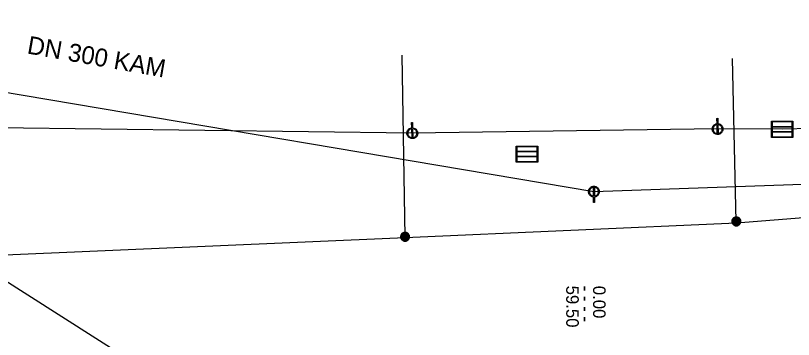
# Model space of a CAD drawing. Extents: x -818321 to -817653, y -1049725 to -1049329.
# Drawn here: x -818121.36 to -818077.89, y -1049423.87 to -1049405.76 of the extents above; entities that cross this region are included whole.
import ezdxf

# ---------------------------------------------------------------- set-up
doc = ezdxf.new("R2010")
doc.units = 0
doc.layers.add('Default', color=7, linetype='Continuous')
doc.layers.add('Level 0', color=7, linetype='Continuous')

msp = doc.modelspace()

# ---------------------------------------------------------------- linework, layer by layer
at = {"layer": 'Default'}
for points in [[(-818099.225, -1049412.037), (-818099.235, -1049411.736), (-818099.186, -1049411.735), (-818099.176, -1049412.035)], [(-818082.16, -1049411.806), (-818082.165, -1049411.506), (-818082.116, -1049411.505), (-818082.111, -1049411.805)], [(-818077.923, -1049412.573), (-818079.123, -1049412.574), (-818079.123, -1049411.673), (-818077.923, -1049411.673), (-818077.923, -1049412.573)], [(-818077.96, -1049411.961), (-818077.96, -1049411.71), (-818079.085, -1049411.71), (-818079.085, -1049411.961), (-818077.96, -1049411.961)], [(-818099.206, -1049412.585), (-818099.223, -1049412.088)], [(-818099.174, -1049412.086), (-818099.157, -1049412.583)], [(-818082.15, -1049412.355), (-818082.159, -1049411.857)], [(-818082.11, -1049411.856), (-818082.101, -1049412.354)], [(-818077.96, -1049412.246), (-818077.96, -1049411.998), (-818079.085, -1049411.998), (-818079.085, -1049412.246), (-818077.96, -1049412.246)], [(-818077.96, -1049412.283), (-818079.085, -1049412.283), (-818079.085, -1049412.536), (-818077.96, -1049412.536), (-818077.96, -1049412.283)], [(-818092.183, -1049413.953), (-818093.383, -1049413.954), (-818093.383, -1049413.053), (-818092.183, -1049413.053), (-818092.183, -1049413.953)], [(-818092.22, -1049413.341), (-818092.22, -1049413.09), (-818093.345, -1049413.09), (-818093.345, -1049413.341), (-818092.22, -1049413.341)], [(-818092.22, -1049413.626), (-818092.22, -1049413.378), (-818093.345, -1049413.378), (-818093.345, -1049413.626), (-818092.22, -1049413.626)], [(-818092.22, -1049413.663), (-818093.345, -1049413.663), (-818093.345, -1049413.916), (-818092.22, -1049413.916), (-818092.22, -1049413.663)], [(-818089.065, -1049415.853), (-818089.065, -1049415.356)], [(-818089.015, -1049415.356), (-818089.015, -1049415.853)], [(-818089.015, -1049415.904), (-818089.015, -1049416.205), (-818089.065, -1049416.205), (-818089.065, -1049415.904)]]:
    msp.add_lwpolyline(points, dxfattribs=at)
for points in [[(-818099.176, -1049412.035), (-818099.113, -1049412.037), (-818099.05, -1049412.07), (-818098.977, -1049412.107), (-818098.935, -1049412.177), (-818098.893, -1049412.247), (-818098.89, -1049412.325), (-818098.887, -1049412.403), (-818098.925, -1049412.477), (-818098.963, -1049412.55), (-818099.033, -1049412.591), (-818099.103, -1049412.632), (-818099.179, -1049412.635), (-818099.255, -1049412.638), (-818099.328, -1049412.602), (-818099.401, -1049412.565), (-818099.444, -1049412.495), (-818099.487, -1049412.424), (-818099.49, -1049412.346), (-818099.492, -1049412.268), (-818099.455, -1049412.195), (-818099.418, -1049412.122), (-818099.348, -1049412.08), (-818099.287, -1049412.043), (-818099.225, -1049412.037)], [(-818099.223, -1049412.088), (-818099.272, -1049412.093), (-818099.323, -1049412.124), (-818099.381, -1049412.158), (-818099.411, -1049412.219), (-818099.442, -1049412.279), (-818099.44, -1049412.344), (-818099.438, -1049412.409), (-818099.402, -1049412.468), (-818099.366, -1049412.527), (-818099.305, -1049412.557), (-818099.253, -1049412.583), (-818099.206, -1049412.585)], [(-818099.157, -1049412.583), (-818099.109, -1049412.577), (-818099.059, -1049412.548), (-818099, -1049412.514), (-818098.969, -1049412.453), (-818098.938, -1049412.391), (-818098.94, -1049412.326), (-818098.942, -1049412.261), (-818098.977, -1049412.203), (-818099.012, -1049412.145), (-818099.073, -1049412.115), (-818099.125, -1049412.088), (-818099.174, -1049412.086)], [(-818082.111, -1049411.805), (-818082.048, -1049411.808), (-818081.985, -1049411.842), (-818081.913, -1049411.88), (-818081.872, -1049411.951), (-818081.831, -1049412.022), (-818081.83, -1049412.1), (-818081.829, -1049412.178), (-818081.868, -1049412.251), (-818081.907, -1049412.324), (-818081.978, -1049412.364), (-818082.049, -1049412.404), (-818082.125, -1049412.405), (-818082.2, -1049412.406), (-818082.273, -1049412.369), (-818082.345, -1049412.332), (-818082.387, -1049412.26), (-818082.428, -1049412.189), (-818082.43, -1049412.11), (-818082.431, -1049412.033), (-818082.393, -1049411.96), (-818082.355, -1049411.888), (-818082.284, -1049411.848), (-818082.222, -1049411.811), (-818082.16, -1049411.806)], [(-818082.159, -1049411.857), (-818082.208, -1049411.862), (-818082.259, -1049411.891), (-818082.318, -1049411.925), (-818082.349, -1049411.985), (-818082.381, -1049412.045), (-818082.38, -1049412.11), (-818082.379, -1049412.175), (-818082.344, -1049412.234), (-818082.309, -1049412.294), (-818082.249, -1049412.325), (-818082.198, -1049412.351), (-818082.15, -1049412.355)], [(-818082.101, -1049412.354), (-818082.054, -1049412.349), (-818082.003, -1049412.32), (-818081.943, -1049412.287), (-818081.911, -1049412.227), (-818081.879, -1049412.166), (-818081.88, -1049412.101), (-818081.881, -1049412.036), (-818081.915, -1049411.977), (-818081.949, -1049411.919), (-818082.009, -1049411.887), (-818082.06, -1049411.859), (-818082.11, -1049411.856)], [(-818089.065, -1049415.904), (-818089.127, -1049415.9), (-818089.189, -1049415.865), (-818089.261, -1049415.826), (-818089.3, -1049415.754), (-818089.34, -1049415.683), (-818089.34, -1049415.605), (-818089.34, -1049415.526), (-818089.3, -1049415.454), (-818089.259, -1049415.382), (-818089.188, -1049415.343), (-818089.116, -1049415.305), (-818089.04, -1049415.305), (-818088.964, -1049415.305), (-818088.893, -1049415.343), (-818088.821, -1049415.382), (-818088.78, -1049415.454), (-818088.74, -1049415.526), (-818088.74, -1049415.605), (-818088.74, -1049415.683), (-818088.78, -1049415.754), (-818088.819, -1049415.826), (-818088.891, -1049415.865), (-818088.953, -1049415.9), (-818089.015, -1049415.904)], [(-818089.065, -1049415.356), (-818089.112, -1049415.36), (-818089.164, -1049415.387), (-818089.223, -1049415.42), (-818089.257, -1049415.48), (-818089.29, -1049415.54), (-818089.29, -1049415.605), (-818089.29, -1049415.67), (-818089.257, -1049415.729), (-818089.225, -1049415.788), (-818089.165, -1049415.821), (-818089.114, -1049415.85), (-818089.065, -1049415.853)], [(-818089.015, -1049415.853), (-818088.966, -1049415.85), (-818088.915, -1049415.821), (-818088.855, -1049415.788), (-818088.823, -1049415.729), (-818088.79, -1049415.67), (-818088.79, -1049415.605), (-818088.79, -1049415.54), (-818088.823, -1049415.48), (-818088.857, -1049415.42), (-818088.917, -1049415.387), (-818088.968, -1049415.36), (-818089.015, -1049415.356)], [(-818081.085, -1049417.015), (-818081.022, -1049417.015), (-818080.962, -1049417.047), (-818080.903, -1049417.079), (-818080.869, -1049417.139), (-818080.835, -1049417.199), (-818080.835, -1049417.265), (-818080.835, -1049417.33), (-818080.868, -1049417.389), (-818080.901, -1049417.449), (-818080.96, -1049417.482), (-818081.02, -1049417.515), (-818081.085, -1049417.515), (-818081.15, -1049417.515), (-818081.209, -1049417.482), (-818081.269, -1049417.449), (-818081.302, -1049417.389), (-818081.335, -1049417.33), (-818081.335, -1049417.265), (-818081.335, -1049417.199), (-818081.301, -1049417.139), (-818081.268, -1049417.079), (-818081.208, -1049417.047), (-818081.148, -1049417.015), (-818081.085, -1049417.015)], [(-818081.085, -1049417.038), (-818081.142, -1049417.038), (-818081.196, -1049417.067), (-818081.251, -1049417.096), (-818081.281, -1049417.151), (-818081.311, -1049417.206), (-818081.311, -1049417.265), (-818081.311, -1049417.324), (-818081.282, -1049417.378), (-818081.252, -1049417.431), (-818081.198, -1049417.461), (-818081.144, -1049417.491), (-818081.085, -1049417.491), (-818081.026, -1049417.491), (-818080.972, -1049417.461), (-818080.918, -1049417.431), (-818080.888, -1049417.378), (-818080.858, -1049417.324), (-818080.858, -1049417.265), (-818080.858, -1049417.206), (-818080.889, -1049417.151), (-818080.92, -1049417.096), (-818080.974, -1049417.067), (-818081.028, -1049417.038), (-818081.085, -1049417.038)], [(-818081.085, -1049417.055), (-818081.032, -1049417.055), (-818080.982, -1049417.082), (-818080.932, -1049417.109), (-818080.904, -1049417.16), (-818080.875, -1049417.21), (-818080.875, -1049417.265), (-818080.875, -1049417.319), (-818080.903, -1049417.369), (-818080.93, -1049417.419), (-818080.98, -1049417.447), (-818081.03, -1049417.474), (-818081.085, -1049417.474), (-818081.139, -1049417.474), (-818081.189, -1049417.447), (-818081.239, -1049417.419), (-818081.267, -1049417.369), (-818081.294, -1049417.319), (-818081.294, -1049417.265), (-818081.294, -1049417.21), (-818081.266, -1049417.16), (-818081.238, -1049417.109), (-818081.188, -1049417.082), (-818081.138, -1049417.055), (-818081.085, -1049417.055)], [(-818081.085, -1049417.077), (-818081.163, -1049417.077), (-818081.218, -1049417.132), (-818081.272, -1049417.187), (-818081.272, -1049417.265), (-818081.272, -1049417.343), (-818081.217, -1049417.397), (-818081.163, -1049417.452), (-818081.085, -1049417.452), (-818081.007, -1049417.452), (-818080.952, -1049417.397), (-818080.897, -1049417.343), (-818080.897, -1049417.265), (-818080.897, -1049417.187), (-818080.952, -1049417.132), (-818081.007, -1049417.077), (-818081.085, -1049417.077)], [(-818081.085, -1049417.1), (-818081.017, -1049417.1), (-818080.969, -1049417.148), (-818080.921, -1049417.196), (-818080.921, -1049417.264), (-818080.921, -1049417.332), (-818080.969, -1049417.38), (-818081.017, -1049417.428), (-818081.085, -1049417.428), (-818081.154, -1049417.428), (-818081.202, -1049417.38), (-818081.249, -1049417.332), (-818081.249, -1049417.264), (-818081.249, -1049417.196), (-818081.202, -1049417.148), (-818081.154, -1049417.1), (-818081.085, -1049417.1)], [(-818081.085, -1049417.12), (-818081.145, -1049417.12), (-818081.188, -1049417.162), (-818081.23, -1049417.204), (-818081.23, -1049417.264), (-818081.23, -1049417.324), (-818081.188, -1049417.366), (-818081.145, -1049417.408), (-818081.085, -1049417.408), (-818081.026, -1049417.408), (-818080.983, -1049417.366), (-818080.941, -1049417.324), (-818080.941, -1049417.264), (-818080.941, -1049417.204), (-818080.983, -1049417.162), (-818081.025, -1049417.12), (-818081.085, -1049417.12)], [(-818081.085, -1049417.14), (-818081.033, -1049417.14), (-818080.996, -1049417.176), (-818080.96, -1049417.213), (-818080.96, -1049417.265), (-818080.96, -1049417.317), (-818080.997, -1049417.353), (-818081.033, -1049417.39), (-818081.085, -1049417.39), (-818081.137, -1049417.39), (-818081.173, -1049417.353), (-818081.21, -1049417.317), (-818081.21, -1049417.265), (-818081.21, -1049417.213), (-818081.174, -1049417.176), (-818081.137, -1049417.14), (-818081.085, -1049417.14)], [(-818081.085, -1049417.163), (-818081.127, -1049417.163), (-818081.157, -1049417.193), (-818081.187, -1049417.222), (-818081.187, -1049417.264), (-818081.187, -1049417.307), (-818081.157, -1049417.336), (-818081.127, -1049417.366), (-818081.085, -1049417.366), (-818081.043, -1049417.366), (-818081.013, -1049417.336), (-818080.984, -1049417.307), (-818080.984, -1049417.264), (-818080.984, -1049417.222), (-818081.013, -1049417.193), (-818081.043, -1049417.163), (-818081.085, -1049417.163)], [(-818081.085, -1049417.18), (-818081.05, -1049417.18), (-818081.025, -1049417.205), (-818081.001, -1049417.229), (-818081.001, -1049417.264), (-818081.001, -1049417.3), (-818081.026, -1049417.324), (-818081.05, -1049417.349), (-818081.085, -1049417.349), (-818081.12, -1049417.349), (-818081.145, -1049417.324), (-818081.169, -1049417.3), (-818081.169, -1049417.264), (-818081.169, -1049417.229), (-818081.145, -1049417.205), (-818081.12, -1049417.18), (-818081.085, -1049417.18)], [(-818081.085, -1049417.202), (-818081.111, -1049417.202), (-818081.129, -1049417.22), (-818081.147, -1049417.239), (-818081.147, -1049417.265), (-818081.147, -1049417.291), (-818081.129, -1049417.309), (-818081.111, -1049417.327), (-818081.085, -1049417.327), (-818081.059, -1049417.327), (-818081.041, -1049417.309), (-818081.022, -1049417.291), (-818081.022, -1049417.265), (-818081.022, -1049417.239), (-818081.041, -1049417.22), (-818081.059, -1049417.202), (-818081.085, -1049417.202)], [(-818081.085, -1049417.226), (-818081.069, -1049417.226), (-818081.057, -1049417.237), (-818081.046, -1049417.248), (-818081.046, -1049417.265), (-818081.046, -1049417.281), (-818081.057, -1049417.292), (-818081.069, -1049417.304), (-818081.085, -1049417.304), (-818081.101, -1049417.304), (-818081.113, -1049417.292), (-818081.124, -1049417.281), (-818081.124, -1049417.265), (-818081.124, -1049417.248), (-818081.113, -1049417.237), (-818081.101, -1049417.226), (-818081.085, -1049417.226)], [(-818081.085, -1049417.241), (-818081.095, -1049417.241), (-818081.102, -1049417.248), (-818081.109, -1049417.255), (-818081.109, -1049417.265), (-818081.109, -1049417.274), (-818081.102, -1049417.281), (-818081.095, -1049417.288), (-818081.085, -1049417.288), (-818081.075, -1049417.288), (-818081.068, -1049417.281), (-818081.062, -1049417.274), (-818081.062, -1049417.265), (-818081.062, -1049417.255), (-818081.068, -1049417.248), (-818081.075, -1049417.241), (-818081.085, -1049417.241)], [(-818099.592, -1049417.874), (-818099.529, -1049417.874), (-818099.469, -1049417.906), (-818099.41, -1049417.938), (-818099.376, -1049417.999), (-818099.342, -1049418.059), (-818099.342, -1049418.124), (-818099.342, -1049418.189), (-818099.375, -1049418.249), (-818099.408, -1049418.308), (-818099.467, -1049418.341), (-818099.527, -1049418.374), (-818099.592, -1049418.374), (-818099.657, -1049418.374), (-818099.716, -1049418.341), (-818099.776, -1049418.308), (-818099.809, -1049418.249), (-818099.842, -1049418.189), (-818099.842, -1049418.124), (-818099.842, -1049418.059), (-818099.808, -1049417.999), (-818099.775, -1049417.938), (-818099.715, -1049417.906), (-818099.655, -1049417.874), (-818099.592, -1049417.874)], [(-818099.592, -1049417.897), (-818099.649, -1049417.897), (-818099.703, -1049417.927), (-818099.758, -1049417.956), (-818099.788, -1049418.01), (-818099.818, -1049418.065), (-818099.818, -1049418.124), (-818099.818, -1049418.183), (-818099.789, -1049418.237), (-818099.759, -1049418.291), (-818099.705, -1049418.321), (-818099.651, -1049418.351), (-818099.592, -1049418.351), (-818099.533, -1049418.351), (-818099.479, -1049418.321), (-818099.425, -1049418.291), (-818099.395, -1049418.237), (-818099.365, -1049418.183), (-818099.365, -1049418.124), (-818099.365, -1049418.065), (-818099.396, -1049418.01), (-818099.427, -1049417.956), (-818099.481, -1049417.927), (-818099.535, -1049417.897), (-818099.592, -1049417.897)], [(-818099.592, -1049417.914), (-818099.539, -1049417.914), (-818099.489, -1049417.941), (-818099.439, -1049417.968), (-818099.411, -1049418.019), (-818099.382, -1049418.069), (-818099.382, -1049418.124), (-818099.382, -1049418.179), (-818099.41, -1049418.228), (-818099.437, -1049418.278), (-818099.487, -1049418.306), (-818099.537, -1049418.333), (-818099.592, -1049418.333), (-818099.646, -1049418.333), (-818099.696, -1049418.306), (-818099.746, -1049418.278), (-818099.774, -1049418.228), (-818099.801, -1049418.179), (-818099.801, -1049418.124), (-818099.801, -1049418.069), (-818099.773, -1049418.019), (-818099.745, -1049417.968), (-818099.695, -1049417.941), (-818099.645, -1049417.914), (-818099.592, -1049417.914)], [(-818099.592, -1049417.936), (-818099.67, -1049417.936), (-818099.725, -1049417.991), (-818099.779, -1049418.046), (-818099.779, -1049418.124), (-818099.779, -1049418.202), (-818099.724, -1049418.257), (-818099.67, -1049418.311), (-818099.592, -1049418.311), (-818099.514, -1049418.311), (-818099.459, -1049418.257), (-818099.404, -1049418.202), (-818099.404, -1049418.124), (-818099.404, -1049418.046), (-818099.459, -1049417.991), (-818099.514, -1049417.936), (-818099.592, -1049417.936)], [(-818099.592, -1049417.959), (-818099.524, -1049417.959), (-818099.476, -1049418.007), (-818099.428, -1049418.055), (-818099.428, -1049418.123), (-818099.428, -1049418.192), (-818099.476, -1049418.24), (-818099.524, -1049418.288), (-818099.592, -1049418.288), (-818099.661, -1049418.288), (-818099.709, -1049418.24), (-818099.756, -1049418.192), (-818099.756, -1049418.123), (-818099.756, -1049418.055), (-818099.709, -1049418.007), (-818099.661, -1049417.959), (-818099.592, -1049417.959)], [(-818099.592, -1049417.979), (-818099.652, -1049417.979), (-818099.695, -1049418.021), (-818099.737, -1049418.064), (-818099.737, -1049418.123), (-818099.737, -1049418.183), (-818099.695, -1049418.226), (-818099.652, -1049418.268), (-818099.592, -1049418.268), (-818099.533, -1049418.268), (-818099.49, -1049418.226), (-818099.448, -1049418.183), (-818099.448, -1049418.123), (-818099.448, -1049418.064), (-818099.49, -1049418.021), (-818099.532, -1049417.979), (-818099.592, -1049417.979)], [(-818099.592, -1049417.999), (-818099.54, -1049417.999), (-818099.503, -1049418.036), (-818099.467, -1049418.072), (-818099.467, -1049418.124), (-818099.467, -1049418.176), (-818099.504, -1049418.212), (-818099.54, -1049418.249), (-818099.592, -1049418.249), (-818099.644, -1049418.249), (-818099.68, -1049418.212), (-818099.717, -1049418.176), (-818099.717, -1049418.124), (-818099.717, -1049418.072), (-818099.681, -1049418.036), (-818099.644, -1049417.999), (-818099.592, -1049417.999)], [(-818099.592, -1049418.022), (-818099.634, -1049418.022), (-818099.664, -1049418.052), (-818099.694, -1049418.081), (-818099.694, -1049418.124), (-818099.694, -1049418.166), (-818099.664, -1049418.196), (-818099.634, -1049418.225), (-818099.592, -1049418.225), (-818099.55, -1049418.225), (-818099.52, -1049418.196), (-818099.491, -1049418.166), (-818099.491, -1049418.124), (-818099.491, -1049418.081), (-818099.52, -1049418.052), (-818099.55, -1049418.022), (-818099.592, -1049418.022)], [(-818099.592, -1049418.039), (-818099.557, -1049418.039), (-818099.532, -1049418.064), (-818099.508, -1049418.089), (-818099.508, -1049418.124), (-818099.508, -1049418.159), (-818099.533, -1049418.183), (-818099.557, -1049418.208), (-818099.592, -1049418.208), (-818099.627, -1049418.208), (-818099.652, -1049418.183), (-818099.676, -1049418.159), (-818099.676, -1049418.124), (-818099.676, -1049418.089), (-818099.652, -1049418.064), (-818099.627, -1049418.039), (-818099.592, -1049418.039)], [(-818099.592, -1049418.061), (-818099.618, -1049418.061), (-818099.636, -1049418.08), (-818099.654, -1049418.098), (-818099.654, -1049418.124), (-818099.654, -1049418.15), (-818099.636, -1049418.168), (-818099.618, -1049418.186), (-818099.592, -1049418.186), (-818099.566, -1049418.186), (-818099.548, -1049418.168), (-818099.529, -1049418.15), (-818099.529, -1049418.124), (-818099.529, -1049418.098), (-818099.548, -1049418.08), (-818099.566, -1049418.061), (-818099.592, -1049418.061)], [(-818099.592, -1049418.085), (-818099.576, -1049418.085), (-818099.564, -1049418.096), (-818099.553, -1049418.107), (-818099.553, -1049418.124), (-818099.553, -1049418.14), (-818099.564, -1049418.152), (-818099.576, -1049418.163), (-818099.592, -1049418.163), (-818099.608, -1049418.163), (-818099.62, -1049418.152), (-818099.631, -1049418.14), (-818099.631, -1049418.124), (-818099.631, -1049418.107), (-818099.62, -1049418.096), (-818099.608, -1049418.085), (-818099.592, -1049418.085)], [(-818099.592, -1049418.101), (-818099.602, -1049418.101), (-818099.609, -1049418.107), (-818099.616, -1049418.114), (-818099.616, -1049418.124), (-818099.616, -1049418.134), (-818099.609, -1049418.141), (-818099.602, -1049418.147), (-818099.592, -1049418.147), (-818099.582, -1049418.147), (-818099.575, -1049418.141), (-818099.569, -1049418.134), (-818099.569, -1049418.124), (-818099.569, -1049418.114), (-818099.575, -1049418.107), (-818099.582, -1049418.101), (-818099.592, -1049418.101)]]:
    msp.add_open_spline(points, degree=3, dxfattribs=at)
at = {"layer": 'Level 0'}
for p, q in [((-818089.04, -1049415.61), (-818147.5, -1049405.76)), ((-818099.592, -1049418.124), (-818099.763, -1049407.976)), ((-818081.085, -1049417.264), (-818081.295, -1049408.152)), ((-818042.42, -1049411.29), (-818078.53, -1049412.12)), ((-818099.19, -1049412.33), (-818127.61, -1049411.97)), ((-818082.13, -1049412.1), (-818099.19, -1049412.33)), ((-818078.53, -1049412.12), (-818082.13, -1049412.1)), ((-818050.71, -1049414.28), (-818089.04, -1049415.61)), ((-818081.083, -1049417.349), (-818059.723, -1049415.639)), ((-818111.68, -1049427.1), (-818127.86, -1049416.83)), ((-818099.591, -1049418.159), (-818081.083, -1049417.349)), ((-818081.083, -1049417.349), (-818081.085, -1049417.264)), ((-818122.833, -1049419.176), (-818099.591, -1049418.159)), ((-818099.591, -1049418.159), (-818099.592, -1049418.124))]:
    msp.add_line(p, q, dxfattribs=at)

# ---------------------------------------------------------------- texts
for s, height, rotation, p in [('DN 300 KAM', 1, 350, (-818120.756, -1049407.874)), ('59.50', 0.7, 270, (-818090.589, -1049420.857)), ('- - - -', 0.7, 270, (-818089.839, -1049420.862)), ('0.00', 0.7, 270, (-818089.089, -1049420.867))]:
    msp.add_text(s, height=height, rotation=rotation, dxfattribs=at).set_placement(p)

doc.saveas('drawing.dxf')
